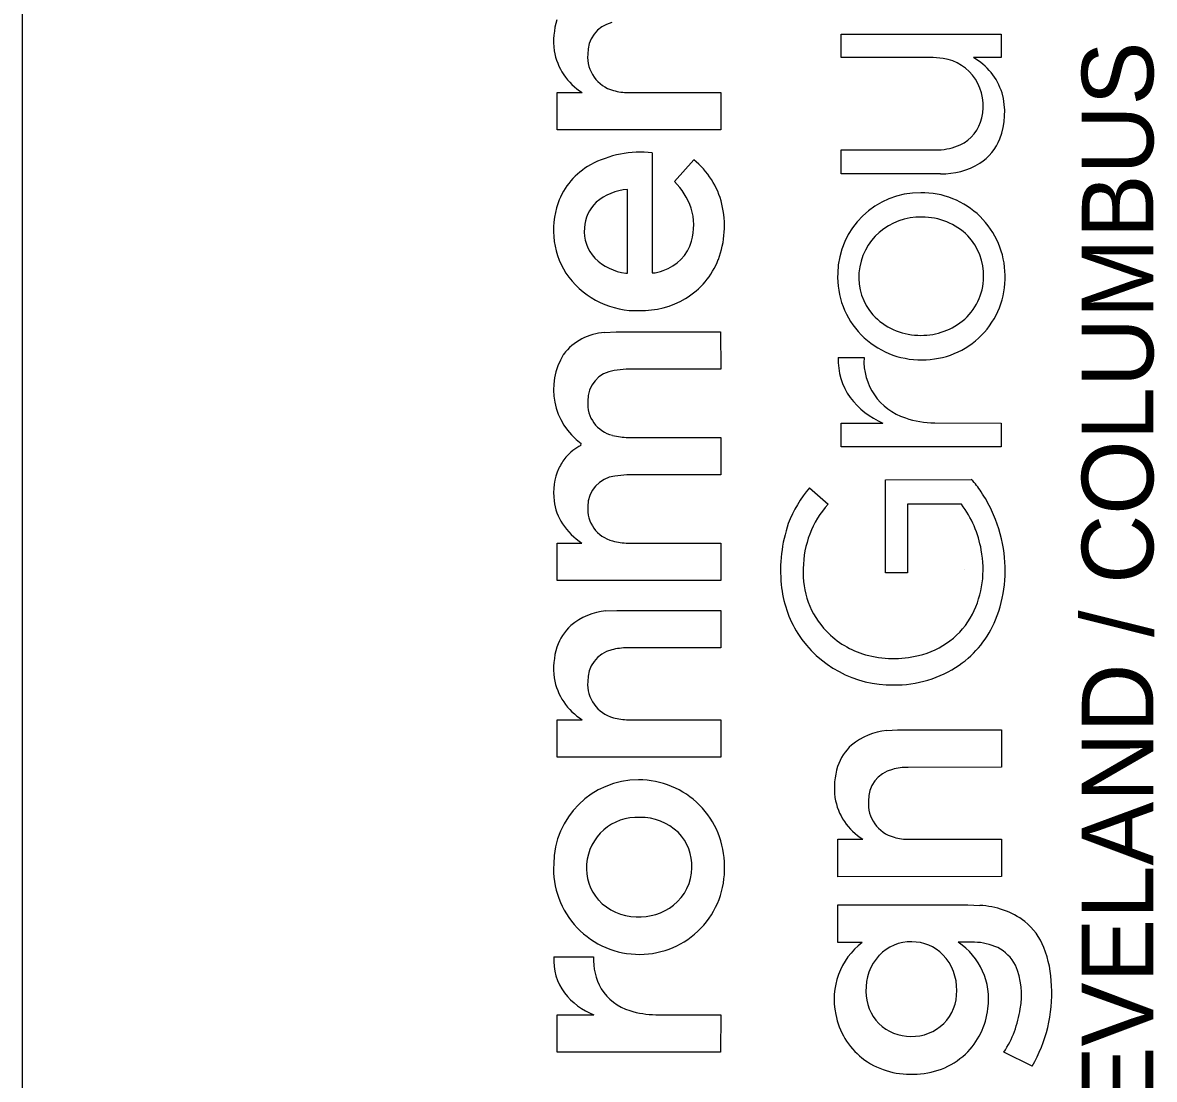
# Model space of a CAD drawing. Extents: x 0 to 34, y 0 to 22.
# Drawn here: x 32 to 32.901, y 3.094 to 3.936 of the extents above; entities that cross this region are included whole.
import ezdxf

# ---------------------------------------------------------------- set-up
doc = ezdxf.new("R2010")
doc.units = 0
doc.layers.add('SH_Border', color=7, linetype='Continuous')
doc.layers.add('SH_Data', color=7, linetype='Continuous')

msp = doc.modelspace()

# ---------------------------------------------------------------- linework, layer by layer
at = {"layer": 'SH_Border'}
msp.add_line((32, 0.5), (32, 21.5), dxfattribs=at)
at = {"layer": 'SH_Data'}
for p, q in [((32.65152, 3.90801), (32.65153, 3.92672)), ((32.65153, 3.92672), (32.7791, 3.92664)), ((32.7791, 3.92664), (32.77908, 3.90796)), ((32.7249, 3.90796), (32.65152, 3.90801)), ((32.7328, 3.90727), (32.7249, 3.90796)), ((32.77908, 3.90796), (32.75689, 3.90796)), ((32.42542, 3.88016), (32.44552, 3.88021)), ((32.42542, 3.85035), (32.42542, 3.88016)), ((32.48222, 3.88021), (32.55569, 3.88021)), ((32.55569, 3.88021), (32.55571, 3.85045)), ((32.55571, 3.85045), (32.42542, 3.85035)), ((32.50108, 3.83209), (32.50118, 3.73657)), ((32.65154, 3.83443), (32.72905, 3.8345)), ((32.65165, 3.81543), (32.65154, 3.83443)), ((32.51882, 3.80927), (32.53422, 3.82662)), ((32.73073, 3.81543), (32.65165, 3.81543)), ((32.48144, 3.73644), (32.48144, 3.80296)), ((32.48016, 3.73628), (32.48144, 3.73644)), ((32.46329, 3.68915), (32.47259, 3.68968)), ((32.47259, 3.68968), (32.55557, 3.68968)), ((32.55557, 3.68968), (32.55571, 3.65982)), ((32.64932, 3.66907), (32.66978, 3.66907)), ((32.48058, 3.65981), (32.47102, 3.65881)), ((32.55571, 3.65982), (32.48058, 3.65981)), ((32.65152, 3.61699), (32.68476, 3.617)), ((32.65152, 3.598), (32.65152, 3.61699)), ((32.72605, 3.61703), (32.7791, 3.61696)), ((32.7791, 3.61696), (32.77903, 3.598)), ((32.48218, 3.60553), (32.55571, 3.60548)), ((32.55571, 3.60548), (32.55571, 3.57568)), ((32.44443, 3.59922), (32.44455, 3.60072)), ((32.77903, 3.598), (32.65152, 3.598)), ((32.4809, 3.57567), (32.47143, 3.57474)), ((32.55571, 3.57568), (32.4809, 3.57567)), ((32.6868, 3.57185), (32.75516, 3.57192)), ((32.6868, 3.49778), (32.6868, 3.57185)), ((32.62636, 3.56548), (32.64114, 3.55241)), ((32.70448, 3.55241), (32.70432, 3.49775)), ((32.74737, 3.55227), (32.70448, 3.55241)), ((32.42542, 3.49152), (32.42545, 3.52138)), ((32.42545, 3.52138), (32.44515, 3.52138)), ((32.48206, 3.52138), (32.55571, 3.52136)), ((32.55571, 3.52136), (32.55571, 3.49156)), ((32.70432, 3.49775), (32.6868, 3.49778)), ((32.75, 3.5), (32.75, 3.5)), ((32.55571, 3.49156), (32.42542, 3.49152)), ((32.46439, 3.46736), (32.47289, 3.46783)), ((32.47289, 3.46783), (32.55571, 3.46783)), ((32.55571, 3.46783), (32.55571, 3.43804)), ((32.55571, 3.43804), (32.4814, 3.43796)), ((32.42542, 3.38066), (32.44552, 3.38071)), ((32.42542, 3.35086), (32.42542, 3.38066)), ((32.48222, 3.38071), (32.55569, 3.38071)), ((32.55569, 3.38071), (32.55571, 3.35096)), ((32.68784, 3.3722), (32.69634, 3.37266)), ((32.69634, 3.37266), (32.77916, 3.37266)), ((32.77916, 3.37266), (32.77917, 3.34287)), ((32.55571, 3.35096), (32.42542, 3.35086)), ((32.77917, 3.34287), (32.70485, 3.3428)), ((32.64888, 3.2855), (32.66897, 3.28555)), ((32.64888, 3.25569), (32.64888, 3.2855)), ((32.70568, 3.28555), (32.77915, 3.28555)), ((32.77915, 3.28555), (32.77917, 3.25579)), ((32.77917, 3.25579), (32.64888, 3.25569)), ((32.6489, 3.20336), (32.64889, 3.23322)), ((32.64889, 3.23322), (32.75236, 3.23322)), ((32.75236, 3.23322), (32.76191, 3.23285)), ((32.66836, 3.20336), (32.6489, 3.20336)), ((32.75763, 3.20356), (32.74487, 3.20361)), ((32.42299, 3.19193), (32.45454, 3.19193)), ((32.42542, 3.14577), (32.45473, 3.14579)), ((32.42542, 3.11593), (32.42542, 3.14577)), ((32.50413, 3.14581), (32.55571, 3.14573)), ((32.55571, 3.14573), (32.55565, 3.11593)), ((32.55565, 3.11593), (32.42542, 3.11593)), ((32.8036, 3.10491), (32.7812, 3.11598))]:
    msp.add_line(p, q, dxfattribs=at)
for points in [[(32.7328, 3.90727), (32.7249, 3.90796), (32.65152, 3.90801), (32.65153, 3.92672), (32.7791, 3.92664), (32.77908, 3.90796), (32.75689, 3.90796)], [(32.42542, 3.85035), (32.42542, 3.88016), (32.44552, 3.88021)], [(32.48222, 3.88021), (32.55569, 3.88021), (32.55571, 3.85045), (32.42542, 3.85035)], [(32.50108, 3.83209), (32.50118, 3.73657)], [(32.73073, 3.81543), (32.65165, 3.81543), (32.65154, 3.83443), (32.72905, 3.8345)], [(32.51882, 3.80927), (32.53422, 3.82662)], [(32.48016, 3.73628), (32.48144, 3.73644), (32.48144, 3.80296)], [(32.46329, 3.68915), (32.47259, 3.68968), (32.55557, 3.68968), (32.55571, 3.65982), (32.48058, 3.65981), (32.47102, 3.65881)], [(32.64932, 3.66907), (32.66978, 3.66907)], [(32.72605, 3.61703), (32.7791, 3.61696), (32.77903, 3.598), (32.65152, 3.598)], [(32.65152, 3.598), (32.65152, 3.61699), (32.68476, 3.617)], [(32.48218, 3.60553), (32.55571, 3.60548), (32.55571, 3.57568), (32.4809, 3.57567), (32.47143, 3.57474)], [(32.44443, 3.59922), (32.44455, 3.60072)], [(32.74737, 3.55227), (32.70448, 3.55241), (32.70432, 3.49775), (32.6868, 3.49778), (32.6868, 3.57185), (32.75516, 3.57192)], [(32.62636, 3.56548), (32.64114, 3.55241)], [(32.42542, 3.49152), (32.42545, 3.52138), (32.44515, 3.52138)], [(32.48206, 3.52138), (32.55571, 3.52136), (32.55571, 3.49156), (32.42542, 3.49152)], [(32.46439, 3.46736), (32.47289, 3.46783), (32.55571, 3.46783), (32.55571, 3.43804), (32.4814, 3.43796)], [(32.42542, 3.35086), (32.42542, 3.38066), (32.44552, 3.38071)], [(32.48222, 3.38071), (32.55569, 3.38071), (32.55571, 3.35096), (32.42542, 3.35086)], [(32.68784, 3.3722), (32.69634, 3.37266), (32.77916, 3.37266), (32.77917, 3.34287), (32.70485, 3.3428)], [(32.64888, 3.25569), (32.64888, 3.2855), (32.66897, 3.28555)], [(32.70568, 3.28555), (32.77915, 3.28555), (32.77917, 3.25579), (32.64888, 3.25569)], [(32.66836, 3.20336), (32.6489, 3.20336), (32.64889, 3.23322), (32.75236, 3.23322), (32.76191, 3.23285)], [(32.75763, 3.20356), (32.74487, 3.20361)], [(32.42299, 3.19193), (32.45454, 3.19193)], [(32.50413, 3.14581), (32.55571, 3.14573), (32.55565, 3.11593), (32.42542, 3.11593)], [(32.42542, 3.11593), (32.42542, 3.14577), (32.45473, 3.14579)], [(32.8036, 3.10491), (32.7812, 3.11598)]]:
    msp.add_lwpolyline(points, dxfattribs=at)
for centre, radius, start, end in [((32.47872, 3.92108), 0.05602, 162.27398, 187.79173), ((32.47872, 3.92108), 0.05602, 162.27398, 187.79173), ((32.47482, 3.91155), 0.02498, 103.68683, 182.21395), ((32.47482, 3.91155), 0.02498, 103.68683, 182.21395), ((32.47027, 3.9209), 0.04763, 188.96462, 238.69865), ((32.47027, 3.9209), 0.04763, 188.96462, 238.69865), ((32.47735, 3.90846), 0.02757, 175.58441, 255.13816), ((32.47735, 3.90846), 0.02757, 175.58441, 255.13816), ((32.72711, 3.86998), 0.03772, 33.50082, 81.32954), ((32.72711, 3.86998), 0.03772, 33.50082, 81.32954), ((32.73239, 3.86485), 0.04959, 17.62209, 60.38974), ((32.73239, 3.86485), 0.04959, 17.62209, 60.38974), ((32.72414, 3.8695), 0.04048, 346.56179, 31.75389), ((32.72414, 3.8695), 0.04048, 346.56179, 31.75389), ((32.48183, 3.92235), 0.04215, 254.08913, 270.52838), ((32.48183, 3.92235), 0.04215, 254.08913, 270.52838), ((32.72343, 3.86415), 0.05838, 339.16197, 15.61485), ((32.72343, 3.86415), 0.05838, 339.16197, 15.61485), ((32.73371, 3.86616), 0.03042, 294.63214, 348.48625), ((32.73371, 3.86616), 0.03042, 294.63214, 348.48625), ((32.72747, 3.88081), 0.04633, 271.95199, 294.08943), ((32.72747, 3.88081), 0.04633, 271.95199, 294.08943), ((32.739, 3.85901), 0.04201, 303.10391, 338.15613), ((32.739, 3.85901), 0.04201, 303.10391, 338.15613), ((32.49176, 3.74874), 0.08387, 83.62118, 118.28448), ((32.49176, 3.74874), 0.08387, 83.62118, 118.28448), ((32.47894, 3.77368), 0.05583, 118.82935, 160.62242), ((32.47894, 3.77368), 0.05583, 118.82935, 160.62242), ((32.49399, 3.7763), 0.06443, 13.53275, 51.36266), ((32.49399, 3.7763), 0.06443, 13.53275, 51.36266), ((32.7321, 3.87256), 0.05715, 268.62699, 301.47779), ((32.7321, 3.87256), 0.05715, 268.62699, 301.47779), ((32.4844, 3.76071), 0.04236, 94.01311, 130.88062), ((32.4844, 3.76071), 0.04236, 94.01311, 130.88062), ((32.48033, 3.77018), 0.05485, 19.0387, 45.44322), ((32.48033, 3.77018), 0.05485, 19.0387, 45.44322), ((32.71435, 3.73484), 0.06552, 89.48213, 178.77752), ((32.71435, 3.73484), 0.06552, 89.48213, 178.77752), ((32.71582, 3.73414), 0.06623, 0.42265, 90.7613), ((32.71582, 3.73414), 0.06623, 0.42265, 90.7613), ((32.48697, 3.77074), 0.06438, 160.52138, 215.78155), ((32.48697, 3.77074), 0.06438, 160.52138, 215.78155), ((32.47703, 3.7709), 0.02985, 132.98553, 177.1802), ((32.47703, 3.7709), 0.02985, 132.98553, 177.1802), ((32.48724, 3.77433), 0.04701, 344.60723, 17.00675), ((32.48724, 3.77433), 0.04701, 344.60723, 17.00675), ((32.48289, 3.77384), 0.0758, 339.35431, 13.37708), ((32.48289, 3.77384), 0.0758, 339.35431, 13.37708), ((32.71397, 3.73244), 0.04846, 87.68827, 175.01696), ((32.71397, 3.73244), 0.04846, 87.68827, 175.01696), ((32.71659, 3.73036), 0.05052, 44.91202, 90.75914), ((32.71659, 3.73036), 0.05052, 44.91202, 90.75914), ((32.47824, 3.76966), 0.03114, 175.00138, 223.2876), ((32.47824, 3.76966), 0.03114, 175.00138, 223.2876), ((32.71955, 3.73452), 0.04549, 358.32279, 43.83486), ((32.71955, 3.73452), 0.04549, 358.32279, 43.83486), ((32.49895, 3.77177), 0.03504, 288.01084, 343.55364), ((32.49895, 3.77177), 0.03504, 288.01084, 343.55364), ((32.48546, 3.77826), 0.04232, 225.06454, 262.79701), ((32.48546, 3.77826), 0.04232, 225.06454, 262.79701), ((32.49548, 3.76982), 0.0626, 300.94393, 338.73223), ((32.49548, 3.76982), 0.0626, 300.94393, 338.73223), ((32.48908, 3.77516), 0.06872, 217.74341, 271.65606), ((32.48908, 3.77516), 0.06872, 217.74341, 271.65606), ((32.50129, 3.75678), 0.02021, 269.70042, 294.87295), ((32.50129, 3.75678), 0.02021, 269.70042, 294.87295), ((32.71483, 3.7334), 0.06606, 177.53728, 270.94524), ((32.71483, 3.7334), 0.06606, 177.53728, 270.94524), ((32.71085, 3.73311), 0.0453, 175.51467, 221.42047), ((32.71085, 3.73311), 0.0453, 175.51467, 221.42047), ((32.71671, 3.73271), 0.06536, 269.30834, 1.67905), ((32.71671, 3.73271), 0.06536, 269.30834, 1.67905), ((32.71931, 3.73374), 0.04572, 308.90382, 359.30947), ((32.71931, 3.73374), 0.04572, 308.90382, 359.30947), ((32.49204, 3.77702), 0.07055, 269.20529, 300.33566), ((32.49204, 3.77702), 0.07055, 269.20529, 300.33566), ((32.71399, 3.73734), 0.05046, 222.66255, 268.37331), ((32.71399, 3.73734), 0.05046, 222.66255, 268.37331), ((32.71567, 3.73859), 0.05178, 266.55312, 308.67253), ((32.71567, 3.73859), 0.05178, 266.55312, 308.67253), ((32.46638, 3.64404), 0.04521, 93.91118, 142.30723), ((32.46638, 3.64404), 0.04521, 93.91118, 142.30723), ((32.47585, 3.64373), 0.05319, 148.28793, 233.9556), ((32.47585, 3.64373), 0.05319, 148.28793, 233.9556), ((32.69878, 3.66662), 0.04952, 177.16211, 216.28024), ((32.69878, 3.66662), 0.04952, 177.16211, 216.28024), ((32.71735, 3.66638), 0.04764, 176.76988, 252.15044), ((32.71735, 3.66638), 0.04764, 176.76988, 252.15044), ((32.47384, 3.63499), 0.02399, 96.75763, 181.6251), ((32.47384, 3.63499), 0.02399, 96.75763, 181.6251), ((32.47577, 3.63241), 0.02597, 175.81573, 256.16716), ((32.47577, 3.63241), 0.02597, 175.81573, 256.16716), ((32.70975, 3.67555), 0.06366, 216.91526, 246.88619), ((32.70975, 3.67555), 0.06366, 216.91526, 246.88619), ((32.7269, 3.69175), 0.07473, 251.13884, 269.34694), ((32.7269, 3.69175), 0.07473, 251.13884, 269.34694), ((32.4817, 3.65053), 0.04501, 254.34629, 270.61033), ((32.4817, 3.65053), 0.04501, 254.34629, 270.61033), ((32.4638, 3.56267), 0.04137, 117.91625, 139.24296), ((32.4638, 3.56267), 0.04137, 117.91625, 139.24296), ((32.46194, 3.56452), 0.03875, 139.52447, 154.84698), ((32.46194, 3.56452), 0.03875, 139.52447, 154.84698), ((32.47144, 3.5612), 0.04877, 156.06382, 187.3493), ((32.47144, 3.5612), 0.04877, 156.06382, 187.3493), ((32.47421, 3.55056), 0.02434, 96.5532, 179.94902), ((32.47421, 3.55056), 0.02434, 96.5532, 179.94902), ((32.72498, 3.53937), 0.04438, 30.98913, 47.16099), ((32.72498, 3.53937), 0.04438, 30.98913, 47.16099), ((32.70163, 3.50187), 0.09855, 139.79476, 159.13696), ((32.70163, 3.50187), 0.09855, 139.79476, 159.13696), ((32.67091, 3.50018), 0.11106, 25.30315, 33.96179), ((32.67091, 3.50018), 0.11106, 25.30315, 33.96179), ((32.46461, 3.55974), 0.04181, 186.5579, 213.38846), ((32.46461, 3.55974), 0.04181, 186.5579, 213.38846), ((32.47608, 3.54863), 0.02628, 175.722, 255.78627), ((32.47608, 3.54863), 0.02628, 175.722, 255.78627), ((32.69899, 3.50079), 0.07753, 138.25804, 179.70064), ((32.69899, 3.50079), 0.07753, 138.25804, 179.70064), ((32.67889, 3.50099), 0.08556, 10.07509, 36.83189), ((32.67889, 3.50099), 0.08556, 10.07509, 36.83189), ((32.6704, 3.49987), 0.11166, 8.80339, 25.33484), ((32.6704, 3.49987), 0.11166, 8.80339, 25.33484), ((32.47886, 3.57078), 0.0598, 214.70433, 235.68724), ((32.47886, 3.57078), 0.0598, 214.70433, 235.68724), ((32.7187, 3.49968), 0.11536, 161.14379, 185.62812), ((32.7187, 3.49968), 0.11536, 161.14379, 185.62812), ((32.48195, 3.56518), 0.0438, 253.66719, 270.14979), ((32.48195, 3.56518), 0.0438, 253.66719, 270.14979), ((32.68425, 3.50057), 0.08036, 333.46689, 11.03668), ((32.68425, 3.50057), 0.08036, 333.46689, 11.03668), ((32.67564, 3.49977), 0.10649, 338.28866, 9.28548), ((32.67564, 3.49977), 0.10649, 338.28866, 9.28548), ((32.68811, 3.49732), 0.06676, 176.66577, 223.6912), ((32.68811, 3.49732), 0.06676, 176.66577, 223.6912), ((32.69336, 3.49699), 0.08987, 185.50773, 212.01294), ((32.69336, 3.49699), 0.08987, 185.50773, 212.01294), ((32.46871, 3.41767), 0.04988, 94.97056, 130.22484), ((32.46871, 3.41767), 0.04988, 94.97056, 130.22484), ((32.69868, 3.49547), 0.0652, 282.88151, 331.81475), ((32.69868, 3.49547), 0.0652, 282.88151, 331.81475), ((32.69835, 3.49168), 0.08241, 305.03061, 337.67573), ((32.69835, 3.49168), 0.08241, 305.03061, 337.67573), ((32.46348, 3.42602), 0.04016, 132.22383, 161.68229), ((32.46348, 3.42602), 0.04016, 132.22383, 161.68229), ((32.69045, 3.50011), 0.07039, 224.02147, 253.88), ((32.69045, 3.50011), 0.07039, 224.02147, 253.88), ((32.69211, 3.49748), 0.08908, 212.70222, 270.71399), ((32.69211, 3.49748), 0.08908, 212.70222, 270.71399), ((32.47872, 3.42158), 0.05602, 162.27398, 187.79173), ((32.47872, 3.42158), 0.05602, 162.27398, 187.79173), ((32.47482, 3.41206), 0.02498, 103.68683, 182.21395), ((32.47482, 3.41206), 0.02498, 103.68683, 182.21395), ((32.48108, 3.39196), 0.04601, 89.60515, 105.33026), ((32.48108, 3.39196), 0.04601, 89.60515, 105.33026), ((32.69318, 3.51254), 0.08309, 254.45353, 283.9512), ((32.69318, 3.51254), 0.08309, 254.45353, 283.9512), ((32.69429, 3.49979), 0.09138, 269.3273, 304.19632), ((32.69429, 3.49979), 0.09138, 269.3273, 304.19632), ((32.47027, 3.42141), 0.04763, 188.96462, 238.69865), ((32.47027, 3.42141), 0.04763, 188.96462, 238.69865), ((32.47735, 3.40897), 0.02757, 175.58441, 255.13816), ((32.47735, 3.40897), 0.02757, 175.58441, 255.13816), ((32.48183, 3.42286), 0.04215, 254.08913, 270.52838), ((32.48183, 3.42286), 0.04215, 254.08913, 270.52838), ((32.69216, 3.32251), 0.04988, 94.97056, 130.22484), ((32.69216, 3.32251), 0.04988, 94.97056, 130.22484), ((32.68694, 3.33085), 0.04016, 132.22383, 161.68229), ((32.68694, 3.33085), 0.04016, 132.22383, 161.68229), ((32.70217, 3.32642), 0.05602, 162.27398, 187.79173), ((32.70217, 3.32642), 0.05602, 162.27398, 187.79173), ((32.70453, 3.29679), 0.04601, 89.60515, 105.33026), ((32.70453, 3.29679), 0.04601, 89.60515, 105.33026), ((32.69828, 3.31689), 0.02498, 103.68683, 182.21395), ((32.69828, 3.31689), 0.02498, 103.68683, 182.21395), ((32.49014, 3.26543), 0.0674, 89.84756, 179.64047), ((32.49014, 3.26543), 0.0674, 89.84756, 179.64047), ((32.49057, 3.26474), 0.0681, 359.54009, 90.21138), ((32.49057, 3.26474), 0.0681, 359.54009, 90.21138), ((32.69372, 3.32624), 0.04763, 188.96462, 238.69865), ((32.69372, 3.32624), 0.04763, 188.96462, 238.69865), ((32.7008, 3.31381), 0.02757, 175.58441, 255.13816), ((32.7008, 3.31381), 0.02757, 175.58441, 255.13816), ((32.48923, 3.26263), 0.0404, 87.04809, 175.57259), ((32.48923, 3.26263), 0.0404, 87.04809, 175.57259), ((32.49204, 3.25999), 0.04299, 45.84264, 90.98008), ((32.49204, 3.25999), 0.04299, 45.84264, 90.98008), ((32.49458, 3.26421), 0.03821, 357.88569, 44.15902), ((32.49458, 3.26421), 0.03821, 357.88569, 44.15902), ((32.70529, 3.32769), 0.04215, 254.08913, 270.52838), ((32.70529, 3.32769), 0.04215, 254.08913, 270.52838), ((32.49083, 3.26209), 0.06819, 176.8344, 270.40384), ((32.49083, 3.26209), 0.06819, 176.8344, 270.40384), ((32.48729, 3.2625), 0.03848, 175.15378, 221.14706), ((32.48729, 3.2625), 0.03848, 175.15378, 221.14706), ((32.49123, 3.26139), 0.06749, 270.06243, 2.37759), ((32.49123, 3.26139), 0.06749, 270.06243, 2.37759), ((32.49446, 3.26318), 0.0383, 308.28936, 359.43468), ((32.49446, 3.26318), 0.0383, 308.28936, 359.43468), ((32.48919, 3.26607), 0.04228, 223.09994, 268.80895), ((32.48919, 3.26607), 0.04228, 223.09994, 268.80895), ((32.49096, 3.2679), 0.04418, 266.56515, 308.06078), ((32.49096, 3.2679), 0.04418, 266.56515, 308.06078), ((32.75907, 3.16789), 0.06503, 53.40344, 87.49062), ((32.75907, 3.16789), 0.06503, 53.40344, 87.49062), ((32.76517, 3.18039), 0.05141, 21.60748, 50.5577), ((32.76517, 3.18039), 0.05141, 21.60748, 50.5577), ((32.70292, 3.15813), 0.05692, 127.37482, 192.22468), ((32.70292, 3.15813), 0.05692, 127.37482, 192.22468), ((32.70693, 3.16927), 0.0346, 88.47302, 136.42562), ((32.70693, 3.16927), 0.0346, 88.47302, 136.42562), ((32.70814, 3.16963), 0.03424, 44.27195, 90.47623), ((32.70814, 3.16963), 0.03424, 44.27195, 90.47623), ((32.71421, 3.15829), 0.05472, 352.1125, 55.92295), ((32.71421, 3.15829), 0.05472, 352.1125, 55.92295), ((32.75666, 3.15725), 0.04633, 65.01687, 88.8011), ((32.75666, 3.15725), 0.04633, 65.01687, 88.8011), ((32.7626, 3.17155), 0.03085, 26.26808, 63.80301), ((32.7626, 3.17155), 0.03085, 26.26808, 63.80301), ((32.73069, 3.16714), 0.08835, 1.15143, 21.3627), ((32.73069, 3.16714), 0.08835, 1.15143, 21.3627), ((32.46616, 3.18882), 0.04329, 175.87313, 216.34747), ((32.46616, 3.18882), 0.04329, 175.87313, 216.34747), ((32.50087, 3.18948), 0.04639, 176.9688, 209.60636), ((32.50087, 3.18948), 0.04639, 176.9688, 209.60636), ((32.71141, 3.16602), 0.0401, 137.46739, 182.33237), ((32.71141, 3.16602), 0.0401, 137.46739, 182.33237), ((32.70368, 3.166), 0.03996, 358.57141, 43.53765), ((32.70368, 3.166), 0.03996, 358.57141, 43.53765), ((32.73565, 3.16154), 0.05953, 349.30734, 23.43071), ((32.73565, 3.16154), 0.05953, 349.30734, 23.43071), ((32.47466, 3.19716), 0.05511, 218.09809, 248.7907), ((32.47466, 3.19716), 0.05511, 218.09809, 248.7907), ((32.49514, 3.18814), 0.04079, 211.94466, 253.2028), ((32.49514, 3.18814), 0.04079, 211.94466, 253.2028), ((32.70645, 3.1637), 0.03511, 178.88208, 271.08374), ((32.70645, 3.1637), 0.03511, 178.88208, 271.08374), ((32.70818, 3.16404), 0.03546, 268.27882, 1.55016), ((32.70818, 3.16404), 0.03546, 268.27882, 1.55016), ((32.70538, 3.16244), 0.11383, 329.6388, 3.25998), ((32.70538, 3.16244), 0.11383, 329.6388, 3.25998), ((32.50465, 3.2165), 0.07069, 252.46555, 269.57296), ((32.50465, 3.2165), 0.07069, 252.46555, 269.57296), ((32.70463, 3.15696), 0.05837, 190.75182, 231.28919), ((32.70463, 3.15696), 0.05837, 190.75182, 231.28919), ((32.70988, 3.15708), 0.05887, 313.74196, 353.8554), ((32.70988, 3.15708), 0.05887, 313.74196, 353.8554), ((32.70738, 3.16334), 0.08771, 327.31495, 351.57478), ((32.70738, 3.16334), 0.08771, 327.31495, 351.57478), ((32.70632, 3.16112), 0.06269, 232.46061, 272.59022), ((32.70632, 3.16112), 0.06269, 232.46061, 272.59022), ((32.70954, 3.15901), 0.06051, 269.6361, 312.70877), ((32.70954, 3.15901), 0.06051, 269.6361, 312.70877)]:
    msp.add_arc(centre, radius, start, end, dxfattribs=at)

# ---------------------------------------------------------------- texts
msp.add_text('AKRON / CLEVELAND / COLUMBUS', height=0.056969, rotation=90, dxfattribs=at).set_placement((32.90012, 2.638))

doc.saveas('drawing.dxf')
